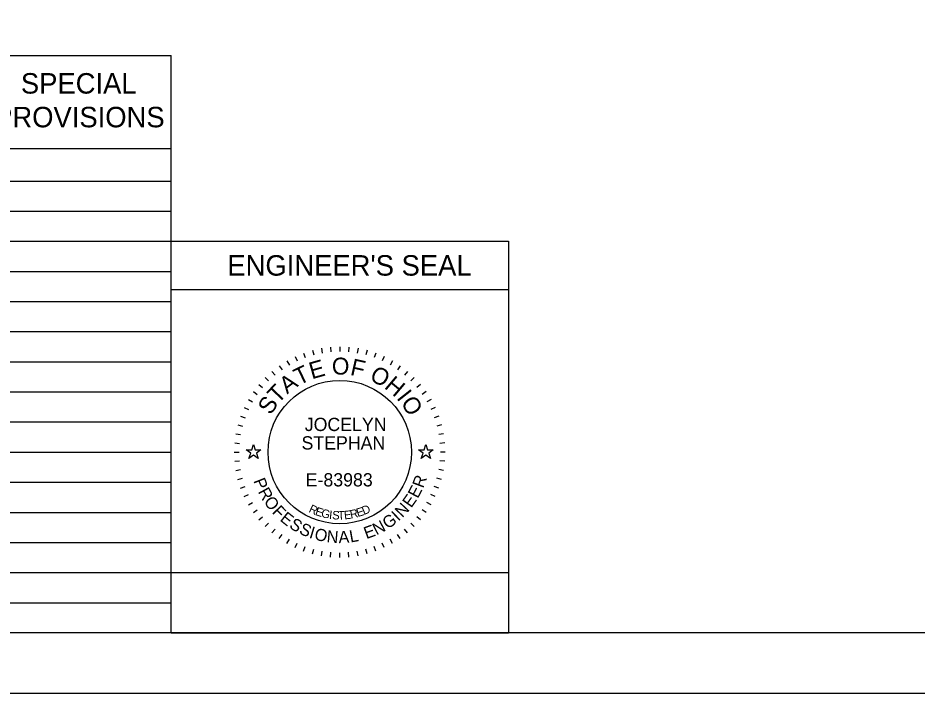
# Model space of a CAD drawing. Extents: x 0 to 34, y 0 to 22.
# Drawn here: x 22.33 to 29.79, y 0 to 5.6 of the extents above; entities that cross this region are included whole.
import ezdxf

# ---------------------------------------------------------------- set-up
doc = ezdxf.new("R2010")
doc.units = 0
for name, color, linetype in [('SH_Border', 7, 'Continuous'), ('SH_Cut_Line', 7, 'Continuous'), ('SH_Data', 7, 'Continuous'), ('SH_Seal', 7, 'Continuous'), ('SH_Text', 7, 'Continuous')]:
    doc.layers.add(name, color=color, linetype=linetype)

msp = doc.modelspace()

# ---------------------------------------------------------------- linework, layer by layer
at = {"layer": 'SH_Border'}
msp.add_lwpolyline([(1.5, 21.5), (33.5, 21.5), (33.5, 0.5), (1.5, 0.5)], close=True, dxfattribs=at)
at = {"layer": 'SH_Cut_Line'}
msp.add_lwpolyline([(0, 0), (34, 0), (34, 22), (0, 22)], close=True, dxfattribs=at)
at = {"layer": 'SH_Data'}
for p, q in [((10.15, 5.2917), (23.6, 5.2917)), ((23.6, 0.5), (23.6, 5.2917)), ((10.15, 4.5209), (23.6, 4.5209)), ((10.15, 4.25), (23.6, 4.25)), ((10.15, 4), (23.6, 4)), ((10.15, 3.75), (23.6, 3.75)), ((23.6, 0.5), (23.6, 3.75)), ((23.6, 3.75), (26.4, 3.75)), ((26.4, 3.75), (26.4, 0.5)), ((10.15, 3.5), (23.6, 3.5)), ((23.6, 3.35), (26.4, 3.35)), ((10.15, 3.25), (23.6, 3.25)), ((10.15, 3), (23.6, 3)), ((10.15, 2.75), (23.6, 2.75)), ((10.15, 2.5), (23.6, 2.5)), ((10.15, 2.25), (23.6, 2.25)), ((10.15, 2), (23.6, 2)), ((10.15, 1.75), (23.6, 1.75)), ((10.15, 1.5), (23.6, 1.5)), ((10.15, 1.25), (23.6, 1.25)), ((10.15, 1), (23.6, 1)), ((10.15, 0.75), (23.6, 0.75)), ((23.6, 0.5), (26.4, 0.5))]:
    msp.add_line(p, q, dxfattribs=at)
msp.add_lwpolyline([(23.6, 0.5), (23.6, 1), (26.4, 1), (26.4, 0.5)], close=True, dxfattribs=at)
at = {"layer": 'SH_Seal'}
for p, q in [((24.7735, 2.8452), (24.7839, 2.8065)), ((24.8481, 2.8617), (24.855, 2.8223)), ((24.9237, 2.8717), (24.9272, 2.8318)), ((25, 2.875), (25, 2.835)), ((25.0763, 2.8717), (25.0728, 2.8318)), ((25.1519, 2.8617), (25.145, 2.8223)), ((25.2265, 2.8452), (25.2161, 2.8065)), ((24.6302, 2.793), (24.6471, 2.7568)), ((24.7007, 2.8222), (24.7144, 2.7846)), ((25.2993, 2.8222), (25.2856, 2.7846)), ((25.3698, 2.793), (25.3529, 2.7568)), ((24.4981, 2.7168), (24.5211, 2.684)), ((24.5625, 2.7578), (24.5825, 2.7231)), ((25.4375, 2.7578), (25.4175, 2.7231)), ((25.5019, 2.7168), (25.4789, 2.684)), ((24.3813, 2.6187), (24.4096, 2.5904)), ((24.4376, 2.6703), (24.4633, 2.6396)), ((25.5624, 2.6703), (25.5367, 2.6396)), ((25.6187, 2.6187), (25.5904, 2.5904)), ((24.3297, 2.5624), (24.3604, 2.5367)), ((25.6703, 2.5624), (25.6396, 2.5367)), ((24.2832, 2.5019), (24.316, 2.4789)), ((25.7168, 2.5019), (25.684, 2.4789)), ((24.2422, 2.4375), (24.2769, 2.4175)), ((25.7578, 2.4375), (25.7231, 2.4175)), ((24.207, 2.3698), (24.2432, 2.3529)), ((25.793, 2.3698), (25.7568, 2.3529)), ((24.1778, 2.2993), (24.2154, 2.2856)), ((25.8222, 2.2993), (25.7846, 2.2856)), ((24.1548, 2.2265), (24.1935, 2.2161)), ((25.8452, 2.2265), (25.8065, 2.2161)), ((24.1383, 2.1519), (24.1777, 2.145)), ((25.8617, 2.1519), (25.8223, 2.145)), ((24.1283, 2.0763), (24.1682, 2.0728)), ((25.8717, 2.0763), (25.8318, 2.0728)), ((24.125, 2), (24.165, 2)), ((25.875, 2), (25.835, 2)), ((24.1283, 1.9237), (24.1682, 1.9272)), ((25.8717, 1.9237), (25.8318, 1.9272)), ((24.1383, 1.8481), (24.1777, 1.855)), ((25.8617, 1.8481), (25.8223, 1.855)), ((24.1548, 1.7735), (24.1935, 1.7839)), ((25.8452, 1.7735), (25.8065, 1.7839)), ((24.1778, 1.7007), (24.2154, 1.7144)), ((24.207, 1.6302), (24.2432, 1.6471)), ((25.793, 1.6302), (25.7568, 1.6471)), ((25.8222, 1.7007), (25.7846, 1.7144)), ((24.2422, 1.5625), (24.2769, 1.5825)), ((25.7578, 1.5625), (25.7231, 1.5825)), ((24.2832, 1.4981), (24.316, 1.5211)), ((25.7168, 1.4981), (25.684, 1.5211)), ((24.3297, 1.4376), (24.3604, 1.4633)), ((25.6703, 1.4376), (25.6396, 1.4633)), ((24.3813, 1.3813), (24.4096, 1.4096)), ((24.4376, 1.3297), (24.4633, 1.3604)), ((25.5624, 1.3297), (25.5367, 1.3604)), ((25.6187, 1.3813), (25.5904, 1.4096)), ((24.4981, 1.2832), (24.5211, 1.316)), ((24.5625, 1.2422), (24.5825, 1.2769)), ((25.4375, 1.2422), (25.4175, 1.2769)), ((25.5019, 1.2832), (25.4789, 1.316)), ((24.6302, 1.207), (24.6471, 1.2432)), ((24.7007, 1.1778), (24.7144, 1.2154)), ((25.2993, 1.1778), (25.2856, 1.2154)), ((25.3698, 1.207), (25.3529, 1.2432)), ((24.7735, 1.1548), (24.7839, 1.1935)), ((24.8481, 1.1383), (24.855, 1.1777)), ((24.9237, 1.1283), (24.9272, 1.1682)), ((25, 1.125), (25, 1.165)), ((25.0763, 1.1283), (25.0728, 1.1682)), ((25.1519, 1.1383), (25.145, 1.1777)), ((25.2265, 1.1548), (25.2161, 1.1935))]:
    msp.add_line(p, q, dxfattribs=at)
for points in [[(24.2236, 2.02), (24.2705, 2.02), (24.285, 2.0645), (24.2995, 2.02), (24.3464, 2.02), (24.3085, 1.9924), (24.323, 1.9478), (24.285, 1.9754), (24.247, 1.9478), (24.2615, 1.9924)], [(25.6536, 2.02), (25.7005, 2.02), (25.715, 2.0645), (25.7295, 2.02), (25.7764, 2.02), (25.7385, 1.9924), (25.753, 1.9478), (25.715, 1.9754), (25.677, 1.9478), (25.6915, 1.9924)]]:
    msp.add_lwpolyline(points, close=True, dxfattribs=at)
msp.add_circle((25, 2), 0.595, dxfattribs=at)

# ---------------------------------------------------------------- texts
at = {"layer": 'SH_Data'}
msp.add_text("ENGINEER'S SEAL", height=0.17, dxfattribs=at).set_placement((24.0676, 3.465))
at = {"layer": 'SH_Seal'}
for s, height, rotation, p in [('E', 0.14, 15.75706, (24.7684, 2.6038)), ('O', 0.14, 359.78119, (24.9347, 2.6443)), ('F', 0.14, 347.43619, (25.0811, 2.6417)), ('T', 0.14, 25.71674, (24.6616, 2.5518)), ('O', 0.14, 332.25863, (25.2398, 2.6015)), ('A', 0.14, 36.47472, (24.5634, 2.4781)), ('H', 0.14, 319.91363, (25.3632, 2.5361)), ('T', 0.14, 46.4344, (24.4883, 2.3964)), ('I', 0.14, 308.36695, (25.4665, 2.4483)), ('S', 0.14, 57.19238, (24.4281, 2.3014)), ('O', 0.14, 303.14906, (25.5021, 2.4089)), ('R', 0.1, 69.23216, (25.6919, 1.6954)), ('P', 0.1, 291.49398, (24.2823, 1.7621)), ('E', 0.1, 61.99508, (25.6476, 1.6098)), ('R', 0.1, 298.73106, (24.319, 1.6717)), ('E', 0.1, 54.75801, (25.5933, 1.5314)), ('O', 0.1, 306.46664, (24.3655, 1.5883)), ('N', 0.1, 47.02243, (25.5202, 1.4508)), ('F', 0.1, 314.7068, (24.4343, 1.4983)), ('E', 0.1, 321.43929, (24.4978, 1.4348)), ('R', 0.07, 334.48695, (24.7375, 1.5051)), ('E', 0.07, 341.03996, (24.7906, 1.4801)), ('G', 0.07, 347.47515, (24.8414, 1.4618)), ('I', 0.07, 353.78581, (24.9091, 1.4468)), ('S', 0.07, 356.89262, (24.9358, 1.4429)), ('T', 0.07, 3.00609, (24.9857, 1.4387)), ('E', 0.07, 6.01169, (25.0389, 1.4412)), ('R', 0.07, 11.91844, (25.0925, 1.4474)), ('E', 0.07, 17.68363, (25.1498, 1.4602)), ('D', 0.07, 23.30524, (25.201, 1.477)), ('I', 0.1, 43.28703, (25.4868, 1.4214)), ('S', 0.1, 328.67637, (24.5743, 1.3752)), ('N', 0.1, 27.31129, (25.3045, 1.3075)), ('G', 0.1, 35.04687, (25.3981, 1.357)), ('S', 0.1, 335.91345, (24.6564, 1.3266)), ('I', 0.1, 343.15053, (24.7406, 1.2897)), ('O', 0.1, 346.88592, (24.7839, 1.2751)), ('N', 0.1, 355.12608, (24.8888, 1.2517)), ('A', 0.1, 2.86166, (24.9923, 1.2437)), ('L', 0.1, 10.09874, (25.0894, 1.249)), ('E', 0.1, 20.07421, (25.2212, 1.277))]:
    msp.add_text(s, height=height, rotation=rotation, dxfattribs=at).set_placement(p)
for s, p in [('JOCELYN', (24.71, 2.1749)), ('STEPHAN', (24.6831, 2.0216)), ('E-83983', (24.7177, 1.7151))]:
    msp.add_text(s, height=0.11, dxfattribs=at).set_placement(p)
at = {"layer": 'SH_Text'}
for s, p in [('SPECIAL', (22.3542, 4.9763)), ('PROVISIONS', (22.1323, 4.6963))]:
    msp.add_text(s, height=0.17, dxfattribs=at).set_placement(p)

doc.saveas('drawing.dxf')
